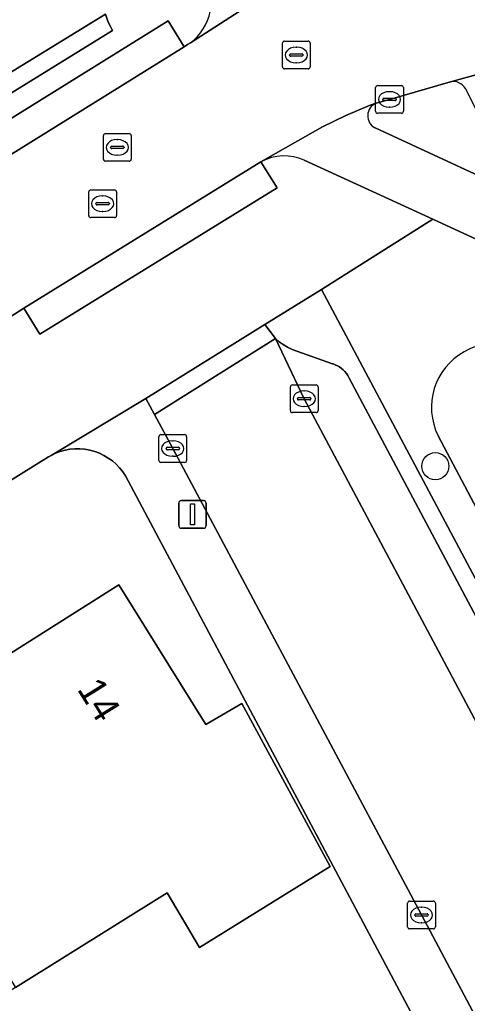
# Model space of a CAD drawing. Extents: x 158835 to 160077, y 386387 to 387778.
# Drawn here: x 159176.76 to 159192.87, y 387158.57 to 387194.01 of the extents above; entities that cross this region are included whole.
import ezdxf

# ---------------------------------------------------------------- set-up
doc = ezdxf.new("R2010")
doc.units = 0
for name, color, linetype in [('IMGEO_Berm_groen', 7, 'Continuous'), ('IMGEO_Boom', 7, 'Continuous'), ('IMGEO_Erf', 7, 'Continuous'), ('IMGEO_Fietspad_gesloten', 7, 'Continuous'), ('IMGEO_Fietspad_open', 7, 'Continuous'), ('IMGEO_Kolk', 7, 'Continuous'), ('IMGEO_Lichtmast', 7, 'Continuous'), ('IMGEO_Muur', 7, 'Continuous'), ('IMGEO_Oever', 7, 'Continuous'), ('IMGEO_Pand', 7, 'Continuous'), ('IMGEO_Pand_nummerreeks', 7, 'Continuous'), ('IMGEO_Parkeervlak_open', 7, 'Continuous'), ('IMGEO_Rijbaan_lokaal_open', 7, 'Continuous'), ('IMGEO_Rioolput', 7, 'Continuous'), ('IMGEO_Verkeerseiland_open', 7, 'Continuous'), ('IMGEO_Voetpad_open', 7, 'Continuous')]:
    doc.layers.add(name, color=color, linetype=linetype)

msp = doc.modelspace()

# ---------------------------------------------------------------- linework, layer by layer
at = {"layer": 'IMGEO_Berm_groen'}
for points in [[(159194.612, 387185.449), (159191.628, 387186.823), (159187.621, 387184.289), (159208.994, 387144.108), (159215.116, 387147.359), (159196.713, 387183.673)], [(159207.68, 387149.036), (159191.821, 387179.017)]]:
    msp.add_lwpolyline(points, dxfattribs=at)
msp.add_arc((159193.884, 387180.042), 2.304, 32.2968, 206.4269, dxfattribs=at)
at = {"layer": 'IMGEO_Boom'}
msp.add_circle((159191.718, 387177.923), 0.489, dxfattribs=at)
at = {"layer": 'IMGEO_Erf'}
for points in [[(159192.812, 387154.528), (159184.858, 387169.495), (159180.565, 387177.574), (159180.465, 387177.724), (159180.352, 387177.865), (159180.227, 387177.995), (159180.091, 387178.113), (159179.944, 387178.219), (159179.789, 387178.311), (159179.627, 387178.389), (159179.458, 387178.452), (159179.284, 387178.5), (159179.106, 387178.532), (159178.926, 387178.548), (159178.746, 387178.548), (159178.566, 387178.532), (159178.388, 387178.5), (159178.214, 387178.452), (159178.045, 387178.389), (159177.883, 387178.311), (159177.794, 387178.26), (159131.832, 387149.649)], [(159151.717, 387157.762), (159154.991, 387159.812), (159155.923, 387158.318), (159158.418, 387159.88), (159160.272, 387161.041), (159159.338, 387162.533), (159162.613, 387164.583), (159163.545, 387163.089), (159166.048, 387164.656), (159167.902, 387165.816), (159166.968, 387167.308), (159170.261, 387169.369), (159171.188, 387167.875), (159180.33, 387173.645), (159183.458, 387168.618), (159184.749, 387169.373), (159187.938, 387163.496), (159183.229, 387160.576), (159182.065, 387162.553), (159176.61, 387159.141), (159168.985, 387154.372)]]:
    msp.add_lwpolyline(points, dxfattribs=at)
at = {"layer": 'IMGEO_Fietspad_gesloten'}
for points in [[(159195.706, 387192.718), (159192.259, 387191.779)], [(159192.799, 387191.53), (159194.081, 387188.983)]]:
    msp.add_lwpolyline(points, dxfattribs=at)
msp.add_arc((159192.36, 387191.287), 0.502, 28.9211, 101.569, dxfattribs=at)
at = {"layer": 'IMGEO_Fietspad_open'}
for points in [[(159182.901, 387193.183), (159186.985, 387195.824)], [(159189.587, 387191.004), (159189.375, 387190.932), (159188.496, 387190.566), (159187.66, 387190.149), (159185.441, 387188.891)], [(159193.435, 387188.315), (159189.553, 387190.113)], [(159187.001, 387188.95), (159191.628, 387186.823), (159194.612, 387185.449)]]:
    msp.add_lwpolyline(points, dxfattribs=at)
for centre, radius, start, end in [((159181.765, 387194.694), 1.89, 306.9466, 348.0447), ((159189.772, 387190.551), 0.49, 112.2369, 243.3925), ((159186.281, 387187.335), 1.768, 65.9668, 118.365)]:
    msp.add_arc(centre, radius, start, end, dxfattribs=at)
at = {"layer": 'IMGEO_Kolk'}
for p, q in [((159189.568, 387190.713), (159189.568, 387191.565)), ((159189.643, 387191.639), (159190.495, 387191.639)), ((159190.056, 387191.419), (159190.081, 387191.419)), ((159190.569, 387191.565), (159190.569, 387190.713)), ((159189.827, 387191.133), (159189.827, 387191.145)), ((159190.265, 387191.096), (159189.867, 387191.096)), ((159189.87, 387191.182), (159190.268, 387191.182)), ((159190.311, 387191.145), (159190.311, 387191.133)), ((159190.495, 387190.639), (159189.643, 387190.639)), ((159190.079, 387190.859), (159190.054, 387190.859)), ((159186.499, 387179.928), (159186.499, 387180.78)), ((159186.574, 387180.854), (159187.426, 387180.854)), ((159187.5, 387180.78), (159187.5, 387179.928)), ((159186.758, 387180.348), (159186.758, 387180.36)), ((159186.801, 387180.397), (159187.199, 387180.397)), ((159186.987, 387180.634), (159187.012, 387180.634)), ((159187.242, 387180.36), (159187.242, 387180.348)), ((159187.196, 387180.311), (159186.798, 387180.311)), ((159187.01, 387180.074), (159186.985, 387180.074)), ((159187.426, 387179.854), (159186.574, 387179.854)), ((159181.764, 387178.135), (159181.764, 387178.987)), ((159181.839, 387179.061), (159182.691, 387179.061)), ((159182.765, 387178.987), (159182.765, 387178.135)), ((159182.066, 387178.604), (159182.464, 387178.604)), ((159182.252, 387178.841), (159182.277, 387178.841)), ((159182.023, 387178.555), (159182.023, 387178.567)), ((159182.461, 387178.518), (159182.063, 387178.518)), ((159182.275, 387178.281), (159182.25, 387178.281)), ((159182.507, 387178.567), (159182.507, 387178.555)), ((159182.691, 387178.061), (159181.839, 387178.061)), ((159190.719, 387161.327), (159190.719, 387162.179)), ((159190.794, 387162.253), (159191.646, 387162.253)), ((159191.207, 387162.033), (159191.232, 387162.033)), ((159191.72, 387162.179), (159191.72, 387161.327)), ((159190.978, 387161.747), (159190.978, 387161.759)), ((159191.416, 387161.71), (159191.018, 387161.71)), ((159191.021, 387161.796), (159191.419, 387161.796)), ((159191.462, 387161.759), (159191.462, 387161.747)), ((159191.646, 387161.253), (159190.794, 387161.253)), ((159191.23, 387161.473), (159191.205, 387161.473))]:
    msp.add_line(p, q, dxfattribs=at)
for points in [[(159189.568, 387190.713), (159189.568, 387191.565)], [(159189.643, 387191.639), (159190.495, 387191.639)], [(159190.569, 387191.565), (159190.569, 387190.713)], [(159190.495, 387190.639), (159189.643, 387190.639)], [(159186.499, 387179.928), (159186.499, 387180.78)], [(159186.574, 387180.854), (159187.426, 387180.854)], [(159187.5, 387180.78), (159187.5, 387179.928)], [(159187.426, 387179.854), (159186.574, 387179.854)], [(159181.764, 387178.135), (159181.764, 387178.987)], [(159181.839, 387179.061), (159182.691, 387179.061)], [(159182.765, 387178.987), (159182.765, 387178.135)], [(159182.691, 387178.061), (159181.839, 387178.061)], [(159190.719, 387161.327), (159190.719, 387162.179)], [(159190.794, 387162.253), (159191.646, 387162.253)], [(159191.72, 387162.179), (159191.72, 387161.327)], [(159191.646, 387161.253), (159190.794, 387161.253)]]:
    msp.add_lwpolyline(points, dxfattribs=at)
for centre, radius, start, end in [((159189.645, 387191.563), 0.0765, 91.552, 178.448), ((159189.645, 387191.563), 0.0765, 91.552, 178.448), ((159190.493, 387191.563), 0.0765, 1.552, 88.448), ((159190.493, 387191.563), 0.0765, 1.552, 88.448), ((159189.867, 387191.142), 0.0403, 85.8775, 175.7526), ((159189.864, 387191.132), 0.0366, 178.938, 274.7102), ((159190.268, 387191.139), 0.043, 264.8664, 352.4533), ((159190.272, 387191.144), 0.0386, 1.7309, 96.639), ((159189.645, 387190.715), 0.0765, 181.552, 268.448), ((159189.645, 387190.715), 0.0765, 181.552, 268.448), ((159190.493, 387190.715), 0.0765, 271.552, 358.448), ((159190.493, 387190.715), 0.0765, 271.552, 358.448), ((159186.576, 387180.778), 0.0765, 91.552, 178.448), ((159186.576, 387180.778), 0.0765, 91.552, 178.448), ((159187.424, 387180.778), 0.0765, 1.552, 88.448), ((159187.424, 387180.778), 0.0765, 1.552, 88.448), ((159186.798, 387180.357), 0.0403, 85.8775, 175.7526), ((159186.795, 387180.347), 0.0366, 178.938, 274.7102), ((159187.199, 387180.354), 0.043, 264.8664, 352.4533), ((159187.203, 387180.359), 0.0386, 1.7309, 96.639), ((159186.576, 387179.93), 0.0765, 181.552, 268.448), ((159186.576, 387179.93), 0.0765, 181.552, 268.448), ((159187.424, 387179.93), 0.0765, 271.552, 358.448), ((159187.424, 387179.93), 0.0765, 271.552, 358.448), ((159181.841, 387178.985), 0.0765, 91.552, 178.448), ((159181.841, 387178.985), 0.0765, 91.552, 178.448), ((159182.689, 387178.985), 0.0765, 1.552, 88.448), ((159182.689, 387178.985), 0.0765, 1.552, 88.448), ((159182.063, 387178.564), 0.0403, 85.8775, 175.7526), ((159182.468, 387178.566), 0.0386, 1.7309, 96.639), ((159182.06, 387178.554), 0.0366, 178.938, 274.7102), ((159182.464, 387178.561), 0.043, 264.8664, 352.4533), ((159181.841, 387178.137), 0.0765, 181.552, 268.448), ((159181.841, 387178.137), 0.0765, 181.552, 268.448), ((159182.689, 387178.137), 0.0765, 271.552, 358.448), ((159182.689, 387178.137), 0.0765, 271.552, 358.448), ((159190.796, 387162.177), 0.0765, 91.552, 178.448), ((159190.796, 387162.177), 0.0765, 91.552, 178.448), ((159191.644, 387162.177), 0.0765, 1.552, 88.448), ((159191.644, 387162.177), 0.0765, 1.552, 88.448), ((159191.018, 387161.756), 0.0403, 85.8775, 175.7526), ((159191.015, 387161.746), 0.0366, 178.938, 274.7102), ((159191.419, 387161.753), 0.043, 264.8664, 352.4533), ((159191.423, 387161.758), 0.0386, 1.7309, 96.639), ((159190.796, 387161.329), 0.0765, 181.552, 268.448), ((159190.796, 387161.329), 0.0765, 181.552, 268.448), ((159191.644, 387161.329), 0.0765, 271.552, 358.448), ((159191.644, 387161.329), 0.0765, 271.552, 358.448)]:
    msp.add_arc(centre, radius, start, end, dxfattribs=at)
for centre, major_axis, ratio, start_param, end_param in [((159190.055, 387191.139), (-0.387, 0.002), 0.722429, 4.712389, 7.853982), ((159190.08, 387191.139), (-0.39, 0.002), 0.717154, 1.570796, 4.712389), ((159186.986, 387180.354), (-0.387, 0.002), 0.722429, 4.712389, 7.853982), ((159187.011, 387180.354), (-0.39, 0.002), 0.717154, 1.570796, 4.712389), ((159182.251, 387178.561), (-0.387, 0.002), 0.722429, 4.712389, 7.853982), ((159182.276, 387178.561), (-0.39, 0.002), 0.717154, 1.570796, 4.712389), ((159191.206, 387161.753), (-0.387, 0.002), 0.722429, 4.712389, 7.853982), ((159191.231, 387161.753), (-0.39, 0.002), 0.717154, 1.570796, 4.712389)]:
    msp.add_ellipse(centre, major_axis=major_axis, ratio=ratio, start_param=start_param, end_param=end_param, dxfattribs=at)
at = {"layer": 'IMGEO_Lichtmast'}
for p, q in [((159182.479, 387175.787), (159182.479, 387176.587)), ((159182.479, 387176.587), (159182.479, 387175.787)), ((159182.579, 387176.687), (159183.369, 387176.687)), ((159183.369, 387176.687), (159182.579, 387176.687)), ((159183.469, 387176.587), (159183.469, 387175.787)), ((159183.469, 387175.787), (159183.469, 387176.587)), ((159183.369, 387175.687), (159182.579, 387175.687)), ((159182.579, 387175.687), (159183.369, 387175.687))]:
    msp.add_line(p, q, dxfattribs=at)
msp.add_lwpolyline([(159182.899, 387176.562), (159183.049, 387176.562), (159183.049, 387175.812), (159182.899, 387175.812), (159182.899, 387176.562)], dxfattribs=at)
for centre, start, end in [((159182.579, 387176.587), 90, 180), ((159182.579, 387176.587), 90, 180), ((159183.369, 387176.587), 0, 90), ((159183.369, 387176.587), 360, 90), ((159182.579, 387175.787), 180, 270), ((159182.579, 387175.787), 180, 270), ((159183.369, 387175.787), 270, 0), ((159183.369, 387175.787), 270, 0)]:
    msp.add_arc(centre, 0.1, start, end, dxfattribs=at)
at = {"layer": 'IMGEO_Muur'}
msp.add_lwpolyline([(159184.858, 387169.495), (159192.812, 387154.528)], dxfattribs=at)
at = {"layer": 'IMGEO_Oever'}
msp.add_lwpolyline([(159191.821, 387179.017), (159207.68, 387149.036)], dxfattribs=at)
msp.add_arc((159193.884, 387180.042), 2.304, 32.2968, 206.4269, dxfattribs=at)
at = {"layer": 'IMGEO_Pand'}
msp.add_lwpolyline([(159184.749, 387169.373), (159183.458, 387168.618), (159180.33, 387173.645), (159171.188, 387167.875), (159176.61, 387159.141), (159182.065, 387162.553), (159183.229, 387160.576), (159187.938, 387163.496)], close=True, dxfattribs=at)
at = {"layer": 'IMGEO_Parkeervlak_open'}
msp.add_lwpolyline([(159217.085, 387127.542), (159188.607, 387181.119), (159188.566, 387181.194), (159188.518, 387181.266), (159188.464, 387181.332), (159188.404, 387181.394), (159188.339, 387181.45), (159188.27, 387181.5), (159188.196, 387181.544), (159188.118, 387181.581), (159188.038, 387181.61), (159188.016, 387181.617), (159186.734, 387182.066), (159186.562, 387182.131), (159186.399, 387182.21), (159186.244, 387182.303), (159186.098, 387182.41), (159185.962, 387182.529), (159186.994, 387180.354), (159195.093, 387165.124)], dxfattribs=at)
at = {"layer": 'IMGEO_Rijbaan_lokaal_open'}
for points in [[(159171.74, 387198.545), (159174.819, 387192.714), (159174.824, 387192.704), (159175.449, 387191.521), (159179.845, 387194.213)], [(159186.985, 387195.824), (159182.901, 387193.183), (159182.797, 387193.116), (159182.679, 387193.04), (159174.039, 387187.668), (159173.315, 387187.218), (159173.218, 387187.157), (159168.759, 387184.361), (159149.771, 387172.508), (159129.852, 387160.089), (159124.698, 387156.88), (159121.887, 387155.13), (159117.406, 387152.34), (159119.888, 387148.372), (159130.485, 387131.344), (159141.225, 387114.195), (159142.231, 387112.577), (159142.423, 387112.239), (159142.602, 387111.89)], [(159185.441, 387188.891), (159187.66, 387190.149), (159188.496, 387190.566), (159189.375, 387190.932), (159189.587, 387191.004), (159190.065, 387191.14), (159192.259, 387191.779), (159195.706, 387192.718)], [(159128.969, 387153.744), (159151.418, 387167.712), (159170.211, 387179.417), (159176.063, 387183.08), (159176.9, 387183.614), (159185.441, 387188.891)], [(159195.093, 387165.124), (159186.994, 387180.354), (159185.962, 387182.529), (159181.607, 387179.789), (159182.263, 387178.561), (159191.217, 387161.754), (159194.383, 387155.794)]]:
    msp.add_lwpolyline(points, dxfattribs=at)
for points in [[(159175.449, 387191.521), (159175.753, 387190.945), (159180.099, 387193.628), (159180.023, 387193.767), (159179.937, 387193.926), (159179.845, 387194.213)], [(159174.039, 387187.668), (159182.679, 387193.04), (159182.098, 387193.974), (159173.458, 387188.602)], [(159176.9, 387183.614), (159177.478, 387182.678), (159186.019, 387187.955), (159185.441, 387188.891)], [(159181.607, 387179.789), (159185.962, 387182.529), (159185.581, 387183.026), (159181.3, 387180.364)]]:
    msp.add_lwpolyline(points, close=True, dxfattribs=at)
at = {"layer": 'IMGEO_Rioolput'}
for p, q in [((159186.214, 387192.314), (159186.214, 387193.166)), ((159186.289, 387193.24), (159187.141, 387193.24)), ((159187.215, 387193.166), (159187.215, 387192.314)), ((159186.516, 387192.783), (159186.914, 387192.783)), ((159186.702, 387193.02), (159186.727, 387193.02)), ((159186.473, 387192.734), (159186.473, 387192.746)), ((159186.911, 387192.697), (159186.513, 387192.697)), ((159186.725, 387192.46), (159186.7, 387192.46)), ((159186.957, 387192.746), (159186.957, 387192.734)), ((159187.141, 387192.24), (159186.289, 387192.24)), ((159179.77, 387188.985), (159179.77, 387189.837)), ((159179.845, 387189.911), (159180.697, 387189.911)), ((159180.258, 387189.691), (159180.283, 387189.691)), ((159180.771, 387189.837), (159180.771, 387188.985)), ((159180.029, 387189.405), (159180.029, 387189.417)), ((159180.467, 387189.368), (159180.069, 387189.368)), ((159180.072, 387189.454), (159180.47, 387189.454)), ((159180.513, 387189.417), (159180.513, 387189.405)), ((159180.697, 387188.911), (159179.845, 387188.911)), ((159180.281, 387189.131), (159180.256, 387189.131)), ((159179.241, 387186.955), (159179.241, 387187.807)), ((159179.316, 387187.881), (159180.168, 387187.881)), ((159180.242, 387187.807), (159180.242, 387186.955)), ((159179.729, 387187.661), (159179.754, 387187.661)), ((159179.5, 387187.375), (159179.5, 387187.387)), ((159179.938, 387187.338), (159179.54, 387187.338)), ((159179.543, 387187.424), (159179.941, 387187.424)), ((159179.752, 387187.101), (159179.727, 387187.101)), ((159179.984, 387187.387), (159179.984, 387187.375)), ((159180.168, 387186.881), (159179.316, 387186.881))]:
    msp.add_line(p, q, dxfattribs=at)
for points in [[(159186.214, 387192.314), (159186.214, 387193.166)], [(159186.289, 387193.24), (159187.141, 387193.24)], [(159187.215, 387193.166), (159187.215, 387192.314)], [(159187.141, 387192.24), (159186.289, 387192.24)], [(159179.77, 387188.985), (159179.77, 387189.837)], [(159179.845, 387189.911), (159180.697, 387189.911)], [(159180.771, 387189.837), (159180.771, 387188.985)], [(159180.697, 387188.911), (159179.845, 387188.911)], [(159179.241, 387186.955), (159179.241, 387187.807)], [(159179.316, 387187.881), (159180.168, 387187.881)], [(159180.242, 387187.807), (159180.242, 387186.955)], [(159180.168, 387186.881), (159179.316, 387186.881)]]:
    msp.add_lwpolyline(points, dxfattribs=at)
for centre, radius, start, end in [((159186.291, 387193.164), 0.0765, 91.552, 178.448), ((159186.291, 387193.164), 0.0765, 91.552, 178.448), ((159187.139, 387193.164), 0.0765, 1.552, 88.448), ((159187.139, 387193.164), 0.0765, 1.552, 88.448), ((159186.513, 387192.743), 0.0403, 85.8775, 175.7526), ((159186.918, 387192.745), 0.0386, 1.7309, 96.639), ((159186.51, 387192.733), 0.0366, 178.938, 274.7102), ((159186.914, 387192.74), 0.043, 264.8664, 352.4533), ((159186.291, 387192.316), 0.0765, 181.552, 268.448), ((159186.291, 387192.316), 0.0765, 181.552, 268.448), ((159187.139, 387192.316), 0.0765, 271.552, 358.448), ((159187.139, 387192.316), 0.0765, 271.552, 358.448), ((159179.847, 387189.835), 0.0765, 91.552, 178.448), ((159179.847, 387189.835), 0.0765, 91.552, 178.448), ((159180.695, 387189.835), 0.0765, 1.552, 88.448), ((159180.695, 387189.835), 0.0765, 1.552, 88.448), ((159180.069, 387189.414), 0.0403, 85.8775, 175.7526), ((159180.066, 387189.404), 0.0366, 178.938, 274.7102), ((159180.47, 387189.411), 0.043, 264.8664, 352.4533), ((159180.474, 387189.416), 0.0386, 1.7309, 96.639), ((159179.847, 387188.987), 0.0765, 181.552, 268.448), ((159179.847, 387188.987), 0.0765, 181.552, 268.448), ((159180.695, 387188.987), 0.0765, 271.552, 358.448), ((159180.695, 387188.987), 0.0765, 271.552, 358.448), ((159179.318, 387187.805), 0.0765, 91.552, 178.448), ((159179.318, 387187.805), 0.0765, 91.552, 178.448), ((159180.166, 387187.805), 0.0765, 1.552, 88.448), ((159180.166, 387187.805), 0.0765, 1.552, 88.448), ((159179.54, 387187.384), 0.0403, 85.8775, 175.7526), ((159179.537, 387187.374), 0.0366, 178.938, 274.7102), ((159179.941, 387187.381), 0.043, 264.8664, 352.4533), ((159179.945, 387187.386), 0.0386, 1.7309, 96.639), ((159179.318, 387186.957), 0.0765, 181.552, 268.448), ((159179.318, 387186.957), 0.0765, 181.552, 268.448), ((159180.166, 387186.957), 0.0765, 271.552, 358.448), ((159180.166, 387186.957), 0.0765, 271.552, 358.448)]:
    msp.add_arc(centre, radius, start, end, dxfattribs=at)
for centre, major_axis, ratio, start_param, end_param in [((159186.701, 387192.74), (-0.387, 0.002), 0.722429, 4.712389, 7.853982), ((159186.726, 387192.74), (-0.39, 0.002), 0.717154, 1.570796, 4.712389), ((159180.257, 387189.411), (-0.387, 0.002), 0.722429, 4.712389, 7.853982), ((159180.282, 387189.411), (-0.39, 0.002), 0.717154, 1.570796, 4.712389), ((159179.728, 387187.381), (-0.387, 0.002), 0.722429, 4.712389, 7.853982), ((159179.753, 387187.381), (-0.39, 0.002), 0.717154, 1.570796, 4.712389)]:
    msp.add_ellipse(centre, major_axis=major_axis, ratio=ratio, start_param=start_param, end_param=end_param, dxfattribs=at)
at = {"layer": 'IMGEO_Verkeerseiland_open'}
for points in [[(159192.259, 387191.779), (159190.065, 387191.14), (159189.587, 387191.004)], [(159194.081, 387188.983), (159192.799, 387191.53)], [(159189.553, 387190.113), (159193.435, 387188.315)]]:
    msp.add_lwpolyline(points, dxfattribs=at)
for centre, radius, start, end in [((159192.36, 387191.287), 0.502, 28.9211, 101.569), ((159189.772, 387190.551), 0.49, 112.2369, 243.3925)]:
    msp.add_arc(centre, radius, start, end, dxfattribs=at)
at = {"layer": 'IMGEO_Voetpad_open'}
for points in [[(159179.845, 387194.213), (159179.937, 387193.926), (159180.023, 387193.767), (159180.099, 387193.628), (159175.753, 387190.945), (159175.449, 387191.521), (159174.824, 387192.704), (159171.72, 387190.674), (159163.598, 387185.605), (159144.069, 387173.416), (159142.799, 387172.623), (159132.839, 387166.407), (159124.595, 387161.262)], [(159173.218, 387187.157), (159173.315, 387187.218), (159174.039, 387187.668), (159173.458, 387188.602), (159182.098, 387193.974), (159182.679, 387193.04), (159182.797, 387193.116), (159182.901, 387193.183)], [(159185.441, 387188.891), (159186.019, 387187.955), (159177.478, 387182.678), (159176.9, 387183.614), (159176.063, 387183.08)], [(159177.794, 387178.26), (159177.883, 387178.311), (159181.3, 387180.364), (159185.581, 387183.026), (159187.621, 387184.289), (159191.628, 387186.823), (159187.001, 387188.95)], [(159208.994, 387144.108), (159187.621, 387184.289), (159185.581, 387183.026), (159185.962, 387182.529), (159186.098, 387182.41), (159186.244, 387182.303), (159186.399, 387182.21), (159186.562, 387182.131), (159186.734, 387182.066), (159188.016, 387181.617), (159188.038, 387181.61), (159188.118, 387181.581), (159188.196, 387181.544), (159188.27, 387181.5), (159188.339, 387181.45), (159188.404, 387181.394), (159188.464, 387181.332), (159188.518, 387181.266), (159188.566, 387181.194), (159188.607, 387181.119), (159217.085, 387127.542)], [(159194.383, 387155.794), (159191.217, 387161.754), (159182.263, 387178.561), (159181.607, 387179.789), (159181.3, 387180.364), (159177.883, 387178.311), (159178.045, 387178.389), (159178.214, 387178.452), (159178.388, 387178.5), (159178.566, 387178.532), (159178.746, 387178.548), (159178.926, 387178.548), (159179.106, 387178.532), (159179.284, 387178.5), (159179.458, 387178.452), (159179.627, 387178.389), (159179.789, 387178.311), (159179.944, 387178.219), (159180.091, 387178.113), (159180.227, 387177.995), (159180.352, 387177.865), (159180.465, 387177.724), (159180.565, 387177.574), (159184.858, 387169.495), (159192.812, 387154.528)], [(159131.832, 387149.649), (159177.794, 387178.26)]]:
    msp.add_lwpolyline(points, dxfattribs=at)
for centre, radius, start, end in [((159181.765, 387194.694), 1.89, 306.9466, 348.0447), ((159186.281, 387187.335), 1.768, 65.9668, 118.365)]:
    msp.add_arc(centre, radius, start, end, dxfattribs=at)

# ---------------------------------------------------------------- texts
at = {"layer": 'IMGEO_Pand_nummerreeks'}
msp.add_text('14', height=1, rotation=301.8906, dxfattribs=at).set_placement((159178.801, 387169.892))

doc.saveas('drawing.dxf')
